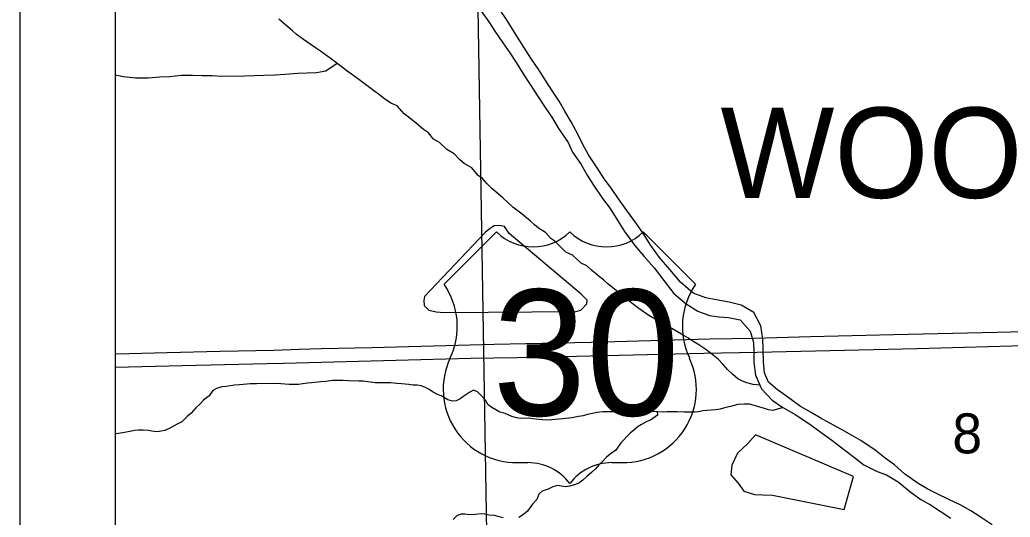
# Model space of a CAD drawing. Extents: x 0 to 34, y 0 to 22.
# Drawn here: x 17.758 to 18.796, y 13.003 to 13.524 of the extents above; entities that cross this region are included whole.
import ezdxf

# ---------------------------------------------------------------- set-up
doc = ezdxf.new("R2010")
doc.units = 0
for name, color, linetype in [('GM_X_Corporation_Text', 7, 'Continuous'), ('GM_X_Major_River', 7, 'Continuous'), ('GM_X_Minor_Lake', 7, 'Continuous'), ('GM_X_Minor_River', 7, 'Continuous'), ('GM_X_Section', 7, 'Continuous'), ('GM_X_Section_Text', 7, 'Continuous'), ('GM_X_US_Route', 7, 'Continuous'), ('GM_X_US_Shield', 7, 'Continuous'), ('SH_Data', 7, 'Continuous')]:
    doc.layers.add(name, color=color, linetype=linetype)

msp = doc.modelspace()

# ---------------------------------------------------------------- linework, layer by layer
at = {"layer": 'GM_X_Major_River'}
for points in [[(18.2396, 13.5359), (18.2495, 13.5223), (18.2564, 13.5117), (18.2641, 13.5004), (18.2717, 13.4899), (18.2782, 13.4797), (18.2855, 13.468), (18.2928, 13.4566), (18.3004, 13.4449), (18.3092, 13.4317), (18.3161, 13.4216), (18.3226, 13.4106), (18.3326, 13.3959), (18.3372, 13.3857), (18.3464, 13.3729), (18.3525, 13.3619), (18.3594, 13.3513), (18.3686, 13.3374), (18.3766, 13.3268), (18.3831, 13.3166), (18.3919, 13.3027), (18.4023, 13.2883), (18.4122, 13.2766), (18.4229, 13.2646), (18.4328, 13.2514), (18.4435, 13.2378), (18.4565, 13.2269), (18.4686, 13.2194), (18.4808, 13.2146), (18.491, 13.2132), (18.5009, 13.2128), (18.513, 13.2103), (18.5233, 13.1982), (18.5268, 13.1865), (18.5273, 13.1763), (18.5273, 13.1656)], [(18.777, 12.9953), (18.7644, 13.004), (18.7549, 13.01), (18.7442, 13.016), (18.7317, 13.0219), (18.7195, 13.0279), (18.7097, 13.0328), (18.6994, 13.0388), (18.6853, 13.0489), (18.6746, 13.0583), (18.6651, 13.0654), (18.6545, 13.0737), (18.6396, 13.0838), (18.6297, 13.0894), (18.6191, 13.0954), (18.6069, 13.1018), (18.597, 13.1074), (18.5875, 13.113), (18.5761, 13.1194), (18.5617, 13.1302), (18.5522, 13.137), (18.5426, 13.1449), (18.5384, 13.1547), (18.5376, 13.1661), (18.5371, 13.1794), (18.5366, 13.19), (18.5346, 13.204), (18.5274, 13.218), (18.514, 13.2255), (18.5015, 13.2288), (18.4879, 13.231), (18.4769, 13.2331), (18.4636, 13.238), (18.4506, 13.2496), (18.4392, 13.2628), (18.4285, 13.2756), (18.4193, 13.2881), (18.4124, 13.2994), (18.4048, 13.3103), (18.3941, 13.3247), (18.3856, 13.3371), (18.378, 13.3477), (18.3704, 13.3579), (18.3638, 13.3684), (18.3539, 13.3832), (18.3481, 13.3937), (18.3431, 13.4039), (18.3359, 13.4175), (18.3293, 13.4289), (18.3232, 13.4391), (18.3163, 13.4496), (18.3087, 13.4617), (18.3018, 13.4719), (18.2937, 13.4843), (18.2861, 13.4957), (18.2777, 13.5092), (18.2688, 13.5236), (18.2608, 13.5357)], [(18.5273, 13.1656), (18.5289, 13.1524), (18.5355, 13.138), (18.5465, 13.126), (18.5568, 13.1192), (18.5705, 13.111), (18.585, 13.1016), (18.599, 13.0915), (18.6089, 13.084), (18.6227, 13.0738), (18.6329, 13.0659), (18.6425, 13.0584), (18.6565, 13.0513), (18.6664, 13.048), (18.6786, 13.0405), (18.6923, 13.0292), (18.7025, 13.0221), (18.7124, 13.0165), (18.7227, 13.0097), (18.7337, 13.0026)]]:
    msp.add_lwpolyline(points, dxfattribs=at)
at = {"layer": 'GM_X_Minor_Lake'}
for points in [[(18.2708, 13.3006), (18.2658, 13.3078), (18.2605, 13.3089), (18.2552, 13.3085), (18.2514, 13.3062), (18.2458, 13.3016), (18.1822, 13.2347), (18.1815, 13.2305), (18.1819, 13.2252), (18.1865, 13.2203), (18.1944, 13.2185), (18.2028, 13.2178), (18.3406, 13.2188), (18.3459, 13.2204), (18.3523, 13.2269), (18.3527, 13.2307), (18.3462, 13.2371)], [(18.3462, 13.2371), (18.2708, 13.3006)], [(18.6219, 13.0116), (18.6319, 13.0462), (18.529, 13.0898), (18.5211, 13.0806), (18.5102, 13.0707), (18.5042, 13.0581), (18.5032, 13.0479), (18.5108, 13.0392), (18.5169, 13.0309), (18.5279, 13.0272), (18.5366, 13.0269), (18.5469, 13.0266)], [(18.5469, 13.0266), (18.6219, 13.0116)]]:
    msp.add_lwpolyline(points, dxfattribs=at)
at = {"layer": 'GM_X_Minor_River'}
for points in [[(18.5337, 13.1419), (18.5267, 13.1425), (18.5198, 13.1443), (18.5156, 13.1458), (18.5106, 13.1484), (18.5048, 13.1532), (18.4998, 13.1581), (18.4948, 13.1638), (18.4898, 13.169), (18.4829, 13.1746), (18.4771, 13.1791), (18.4698, 13.1839), (18.4645, 13.1873), (18.4583, 13.1914), (18.4533, 13.1943), (18.4396, 13.2021), (18.4346, 13.2047), (18.4173, 13.2148), (18.4066, 13.2222), (18.4024, 13.2252), (18.3958, 13.2304), (18.3901, 13.2353), (18.3858, 13.2386), (18.3808, 13.2428), (18.3747, 13.2476), (18.3697, 13.2521), (18.3651, 13.2555), (18.357, 13.2622), (18.3524, 13.2667), (18.3463, 13.2697), (18.3374, 13.2779), (18.3301, 13.2812), (18.3186, 13.2925), (18.3144, 13.2954), (18.3089, 13.3018), (18.3017, 13.3063), (18.2974, 13.3096), (18.2928, 13.3138), (18.289, 13.3171), (18.2844, 13.3209), (18.2748, 13.3283), (18.269, 13.3336), (18.2644, 13.3377), (18.2594, 13.3422), (18.2528, 13.3478), (18.2478, 13.3527), (18.2428, 13.3583), (18.2382, 13.3613), (18.2316, 13.3695), (18.2236, 13.374), (18.219, 13.3777), (18.2132, 13.3841), (18.2055, 13.3886), (18.1978, 13.3961), (18.1917, 13.3994), (18.1863, 13.4062), (18.1809, 13.4095), (18.1732, 13.4162), (18.169, 13.4196), (18.1651, 13.423), (18.1609, 13.426), (18.1536, 13.4342), (18.1467, 13.4372), (18.1402, 13.4416), (18.134, 13.4465), (18.1302, 13.4495), (18.126, 13.4525), (18.1217, 13.4558), (18.1133, 13.4618), (18.1094, 13.4648), (18.1056, 13.4674), (18.101, 13.4707), (18.096, 13.4745), (18.0845, 13.4834), (18.073, 13.4916), (18.068, 13.495), (18.0553, 13.5039), (18.0515, 13.5065), (18.0476, 13.5095), (18.0438, 13.5129), (18.0369, 13.5189), (18.0295, 13.5252)], [(18.0905, 13.4788), (18.0787, 13.4706), (18.0689, 13.469), (18.0492, 13.4681), (18.0359, 13.4672), (18.0257, 13.4664), (18.0136, 13.4663), (18.0038, 13.4658), (17.9935, 13.4654), (17.9697, 13.4652), (17.9594, 13.4659), (17.9492, 13.4658), (17.939, 13.4661), (17.9272, 13.466), (17.9151, 13.4648), (17.9042, 13.4643), (17.8928, 13.4635), (17.8792, 13.4634), (17.8667, 13.4648), (17.8579, 13.4665)], [(18.5581, 13.1185), (18.5472, 13.1154), (18.5426, 13.1158), (18.5384, 13.1172), (18.5327, 13.1191), (18.5266, 13.1209), (18.5227, 13.122), (18.5174, 13.1219), (18.5106, 13.1214), (18.503, 13.1194), (18.4981, 13.1182), (18.492, 13.1166), (18.4871, 13.1158), (18.4825, 13.1157), (18.478, 13.1153), (18.4738, 13.1149), (18.4692, 13.114), (18.465, 13.1136), (18.4544, 13.1135), (18.4468, 13.1137), (18.443, 13.1137), (18.4365, 13.114), (18.4327, 13.1135), (18.4266, 13.1138), (18.4221, 13.1142), (18.3871, 13.1137), (18.3825, 13.114), (18.3692, 13.1138), (18.3627, 13.113), (18.3582, 13.1122), (18.3529, 13.111), (18.3483, 13.1098), (18.3434, 13.1089), (18.3366, 13.1077), (18.3271, 13.1064), (18.3229, 13.106), (18.3157, 13.1055), (18.31, 13.1051), (18.3024, 13.1057), (18.2955, 13.1064), (18.2913, 13.1071), (18.283, 13.107), (18.2784, 13.1077), (18.2738, 13.1091), (18.2665, 13.1121), (18.2612, 13.1135), (18.257, 13.1161), (18.2528, 13.1184), (18.2489, 13.121), (18.2462, 13.1259), (18.2416, 13.1311), (18.2377, 13.1349), (18.2335, 13.1367), (18.2297, 13.1344), (18.2233, 13.1301), (18.2196, 13.1274), (18.2154, 13.1255), (18.2116, 13.125), (18.2066, 13.1265), (18.1997, 13.1306), (18.1959, 13.132), (18.1913, 13.1346), (18.1863, 13.1376), (18.1825, 13.1395), (18.1787, 13.1409), (18.1745, 13.1416), (18.1699, 13.1419), (18.1657, 13.1426), (18.1581, 13.1433), (18.1532, 13.1436), (18.1463, 13.1443), (18.1303, 13.1441), (18.1227, 13.1451), (18.1178, 13.1458), (18.1132, 13.1461), (18.1025, 13.1464), (18.0968, 13.1467), (18.0896, 13.1466), (18.0858, 13.1465), (18.0786, 13.1457), (18.0733, 13.1452), (18.0638, 13.1443), (18.0596, 13.1439), (18.0547, 13.1431), (18.0501, 13.1426), (18.0402, 13.1425), (18.0315, 13.1431), (18.0242, 13.1434), (18.006, 13.1432), (17.9995, 13.1431), (17.9957, 13.1427), (17.9881, 13.1422), (17.9828, 13.1417), (17.9741, 13.1405), (17.9695, 13.14), (17.9642, 13.1381), (17.9601, 13.1361)], [(17.9601, 13.1361), (17.9563, 13.1307), (17.9503, 13.1261), (17.9469, 13.1223), (17.9424, 13.118), (17.9375, 13.1126), (17.9338, 13.1092), (17.9278, 13.1034), (17.9229, 13.101), (17.9157, 13.0971), (17.91, 13.0944), (17.9062, 13.0936), (17.902, 13.0928), (17.8963, 13.0935), (17.8925, 13.0942), (17.8872, 13.0945), (17.8822, 13.0948), (17.8785, 13.0944), (17.8716, 13.0928), (17.8656, 13.0919), (17.8614, 13.0911), (17.8579, 13.0907)], [(18.4261, 13.1139), (18.4263, 13.1104), (18.4191, 13.105), (18.4153, 13.1038), (18.4097, 13.1007), (18.4059, 13.0984), (18.4014, 13.0945), (18.3976, 13.0914), (18.3879, 13.0814), (18.3827, 13.0737), (18.3766, 13.0695), (18.3729, 13.0664), (18.3691, 13.0622), (18.365, 13.0583), (18.3612, 13.0541), (18.3571, 13.0502), (18.3526, 13.0464), (18.3481, 13.0421), (18.3439, 13.039), (18.3394, 13.0375), (18.3341, 13.0359), (18.3299, 13.0354), (18.3257, 13.0358), (18.3215, 13.0368), (18.3166, 13.0353), (18.3117, 13.0329), (18.3056, 13.0309), (18.3019, 13.0275), (18.3, 13.0221), (18.2952, 13.0171), (18.2899, 13.0098), (18.2858, 13.0064), (18.2809, 13.0033)], [(18.2645, 13.0027), (18.2603, 13.0037), (18.2554, 13.0052), (18.25, 13.0055), (18.2455, 13.0066), (18.2417, 13.0069), (18.2352, 13.0064), (18.2291, 13.006), (18.2245, 13.0067), (18.2204, 13.0066), (18.2162, 13.0051), (18.2121, 13.0012)]]:
    msp.add_lwpolyline(points, dxfattribs=at)
at = {"layer": 'GM_X_Section'}
msp.add_lwpolyline([(19.2565, 13.6162), (19.256, 12.6012), (18.2539, 12.6075), (18.2369, 13.6209)], close=True, dxfattribs=at)
at = {"layer": 'GM_X_US_Route'}
for points in [[(17.8579, 13.1745), (17.8725, 13.175), (17.9125, 13.1759), (17.968, 13.1773), (18.0242, 13.1786), (18.0507, 13.1795), (18.0737, 13.18), (18.1268, 13.1813), (18.2173, 13.1836), (18.255, 13.1846), (18.2883, 13.1854), (18.3567, 13.1869), (18.4812, 13.1903), (18.5276, 13.1911), (18.5866, 13.1926), (18.6736, 13.1948), (18.7824, 13.1974), (18.8974, 13.2), (19.0092, 13.2027), (19.0583, 13.2043), (19.0746, 13.2043), (19.1214, 13.2056)], [(17.8579, 13.1605), (17.8857, 13.1613), (17.9426, 13.1628), (18.0173, 13.1645), (18.0342, 13.1649), (18.0871, 13.1661), (18.1521, 13.1679), (18.2305, 13.1699), (18.2794, 13.1706), (18.3415, 13.1722), (18.4749, 13.1753), (18.5309, 13.1764), (18.6984, 13.1803), (18.7978, 13.1829), (18.9039, 13.1862), (18.9282, 13.1867), (18.9614, 13.1879), (19.0178, 13.1892), (19.0711, 13.1905), (19.1215, 13.1917)]]:
    msp.add_lwpolyline(points, dxfattribs=at)
at = {"layer": 'GM_X_US_Shield'}
for p, q in [((18.2575, 13.3023), (18.2026, 13.2474)), ((18.4663, 13.2474), (18.4113, 13.3023)), ((18.2795, 13.0606), (18.2905, 13.0606)), ((18.3784, 13.0606), (18.3894, 13.0606))]:
    msp.add_line(p, q, dxfattribs=at)
for centre, radius, start, end in [((18.296, 13.3415), 0.0549, 225.573, 314.427), ((18.3729, 13.3415), 0.0549, 225.573, 314.427), ((18.1396, 13.2033), 0.0769, 334.5471, 35.0009), ((18.5293, 13.2033), 0.0769, 144.9991, 205.4529), ((18.2786, 13.1375), 0.0769, 154.8319, 270.6383), ((18.3902, 13.1375), 0.0769, 269.3617, 25.1681), ((18.2905, 13.0057), 0.0549, 36.8699, 90), ((18.3784, 13.0057), 0.0549, 90, 143.1301)]:
    msp.add_arc(centre, radius, start, end, dxfattribs=at)
at = {"layer": 'SH_Data'}
for p, q in [((17.7579, 16.0775), (17.7579, 9.0775)), ((17.8579, 15.9775), (17.8579, 9.1775))]:
    msp.add_line(p, q, dxfattribs=at)

# ---------------------------------------------------------------- texts
at = {"layer": 'GM_X_Corporation_Text'}
msp.add_text('WOOSTER', height=0.0947, rotation=0, dxfattribs=at).set_placement((18.4923, 13.3379))
at = {"layer": 'GM_X_Section_Text'}
msp.add_text('8', height=0.0419, rotation=0, dxfattribs=at).set_placement((18.7354, 13.0703))
at = {"layer": 'GM_X_US_Shield'}
msp.add_text('30', height=0.13184, dxfattribs=at).set_placement((18.2535, 13.11))

doc.saveas('drawing.dxf')
